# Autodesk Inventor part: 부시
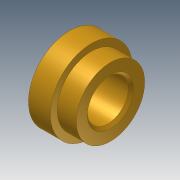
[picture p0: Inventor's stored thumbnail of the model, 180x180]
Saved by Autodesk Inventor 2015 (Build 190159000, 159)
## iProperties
Created: 2011-04
Part Number: 부시
Document SubType Name: Modeling
Density: 1 g/cm^3
Material: 일반
Appearance: 황동 - 새틴
Author: pww
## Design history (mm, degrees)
sketch "스케치1"
  geometry: L1 (0, 0)-(15, 0); L2 (0, 7.5)-(15, 7.5); L3 (15, 7.5)-(15, 12.5); L4 (15, 12.5)-(8, 12.5); L5 (8, 12.5)-(8, 15); L6 (8, 15)-(0, 15); L7 (0, 15)-(0, 7.5)
  constraints: 14 end point, 4 parallel, 2 vertical alignment, 1 horizontal, 1 perpendicular, 1 vertical
  dimensions: "d0" = 15 distance of L1.start L1.end; "d1" = 15 diameter of L2 L1; "d2" = 25 diameter of L4 L1; "d3" = 8 distance of L5.end L6.end; "d4" = 30 diameter of L6 L1
revolve "회전1" sketch "스케치1" stored, may be unused: angle "d5" = 90 deg
chamfer "모따기1" distance "d6" = 1; stored, may be unused: second distance "d7" = 2, angle "d8" = 45 deg
node "솔리드1"
